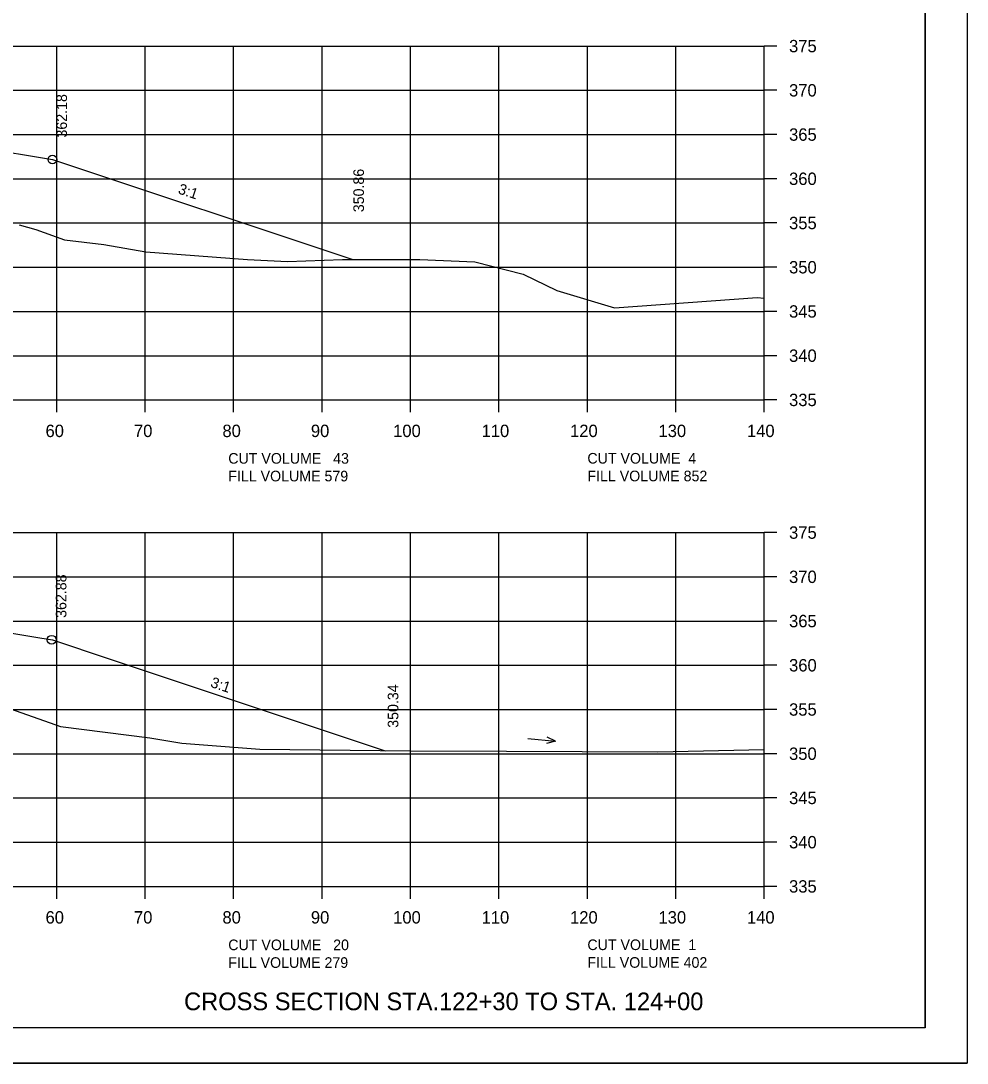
# Model space of a CAD drawing. Extents: x 1374859 to 1376773, y 382242 to 389804.
# Drawn here: x 1376190.5 to 1376297.5, y 384375.1 to 384493 of the extents above; entities that cross this region are included whole.
import ezdxf

# ---------------------------------------------------------------- set-up
doc = ezdxf.new("R2010")
doc.units = 0
for name, color, linetype in [('R_Axis', 7, 'Continuous'), ('R_Axis Annot', 7, 'Continuous'), ('R_Border', 7, 'Continuous'), ('R_Draft', 7, 'Continuous'), ('R_Exist Surface', 7, 'Continuous'), ('R_Fin Surface', 7, 'Continuous'), ('R_Grid', 7, 'Continuous'), ('R_No Plot', 7, 'Continuous'), ('R_Water Annot', 7, 'Continuous'), ('R_Xsect Elev', 7, 'Continuous'), ('R_Xsect Slope', 7, 'Continuous')]:
    doc.layers.add(name, color=color, linetype=linetype)

msp = doc.modelspace()

# ---------------------------------------------------------------- linework, layer by layer
at = {"layer": 'R_Axis'}
for p, q in [((1376274.57, 384450.1), (1376274.57, 384490.1)), ((1376275.97, 384490.1), (1376274.57, 384490.1)), ((1376275.97, 384485.1), (1376274.57, 384485.1)), ((1376275.97, 384480.1), (1376274.57, 384480.1)), ((1376275.97, 384475.1), (1376274.57, 384475.1)), ((1376275.97, 384470.1), (1376274.57, 384470.1)), ((1376275.97, 384465.1), (1376274.57, 384465.1)), ((1376275.97, 384460.1), (1376274.57, 384460.1)), ((1376275.97, 384455.1), (1376274.57, 384455.1)), ((1375994.57, 384450.1), (1376274.57, 384450.1)), ((1376194.57, 384448.7), (1376194.57, 384450.1)), ((1376204.57, 384448.7), (1376204.57, 384450.1)), ((1376214.57, 384448.7), (1376214.57, 384450.1)), ((1376224.57, 384448.7), (1376224.57, 384450.1)), ((1376234.57, 384448.7), (1376234.57, 384450.1)), ((1376244.57, 384448.7), (1376244.57, 384450.1)), ((1376254.57, 384448.7), (1376254.57, 384450.1)), ((1376264.57, 384448.7), (1376264.57, 384450.1)), ((1376274.57, 384448.7), (1376274.57, 384450.1)), ((1376275.97, 384450.1), (1376274.57, 384450.1)), ((1376274.57, 384395.1), (1376274.57, 384435.1)), ((1376275.97, 384435.1), (1376274.57, 384435.1)), ((1376275.97, 384430.1), (1376274.57, 384430.1)), ((1376275.97, 384425.1), (1376274.57, 384425.1)), ((1376275.97, 384420.1), (1376274.57, 384420.1)), ((1376275.97, 384415.1), (1376274.57, 384415.1)), ((1376275.97, 384410.1), (1376274.57, 384410.1)), ((1376275.97, 384405.1), (1376274.57, 384405.1)), ((1376275.97, 384400.1), (1376274.57, 384400.1)), ((1375994.57, 384395.1), (1376274.57, 384395.1)), ((1376194.57, 384393.7), (1376194.57, 384395.1)), ((1376204.57, 384393.7), (1376204.57, 384395.1)), ((1376214.57, 384393.7), (1376214.57, 384395.1)), ((1376224.57, 384393.7), (1376224.57, 384395.1)), ((1376234.57, 384393.7), (1376234.57, 384395.1)), ((1376244.57, 384393.7), (1376244.57, 384395.1)), ((1376254.57, 384393.7), (1376254.57, 384395.1)), ((1376264.57, 384393.7), (1376264.57, 384395.1)), ((1376274.57, 384393.7), (1376274.57, 384395.1)), ((1376275.97, 384395.1), (1376274.57, 384395.1))]:
    msp.add_line(p, q, dxfattribs=at)
at = {"layer": 'R_Border'}
for q in [(1376292.75, 384584.56), (1375976.57, 384379.1)]:
    msp.add_line((1376292.75, 384379.1), q, dxfattribs=at)
at = {"layer": 'R_Exist Surface'}
for points in [[(1376190.33, 384469.88), (1376192.22, 384469.36), (1376195.45, 384468.19), (1376199.89, 384467.66), (1376204.66, 384466.85), (1376216.14, 384465.96), (1376220.67, 384465.74), (1376226.89, 384465.96), (1376235.62, 384465.98), (1376241.83, 384465.72), (1376247.3, 384464.31), (1376251.11, 384462.46), (1376257.64, 384460.52), (1376273.78, 384461.69), (1376274.57, 384461.6)], [(1376189.36, 384415.18), (1376195, 384413.18), (1376205.12, 384411.9), (1376208.73, 384411.28), (1376217.54, 384410.6), (1376234.53, 384410.41), (1376245.43, 384410.37), (1376262.55, 384410.31), (1376274.57, 384410.58)]]:
    msp.add_lwpolyline(points, dxfattribs=at)
at = {"layer": 'R_Fin Surface'}
for points in [[(1376046.15, 384465.48), (1376051.59, 384463.67), (1376075.09, 384471.5), (1376083.13, 384472.85), (1376097.09, 384475.17), (1376105.09, 384475.79), (1376134.59, 384478.06), (1376164.09, 384480.33), (1376172.09, 384480.95), (1376185.9, 384478.64), (1376194.09, 384477.28), (1376228.04, 384465.96)], [(1376064.09, 384413.54), (1376073.29, 384416.61), (1376075.08, 384417.21), (1376081.72, 384418.31), (1376083.13, 384418.55), (1376094.64, 384420.47), (1376097.08, 384420.87), (1376103.69, 384421.38), (1376105.08, 384421.49), (1376110.14, 384421.88), (1376134.58, 384423.76), (1376158.89, 384425.63), (1376164.08, 384426.03), (1376165.47, 384426.14), (1376172.08, 384426.65), (1376183.48, 384424.75), (1376185.9, 384424.35), (1376192.66, 384423.22), (1376194.08, 384422.98), (1376200.51, 384420.84), (1376231.7, 384410.44)]]:
    msp.add_lwpolyline(points, dxfattribs=at)
at = {"layer": 'R_Grid'}
for p, q in [((1375994.57, 384490.1), (1376274.57, 384490.1)), ((1376194.57, 384450.1), (1376194.57, 384490.1)), ((1376204.57, 384450.1), (1376204.57, 384490.1)), ((1376214.57, 384450.1), (1376214.57, 384490.1)), ((1376224.57, 384450.1), (1376224.57, 384490.1)), ((1376234.57, 384450.1), (1376234.57, 384490.1)), ((1376244.57, 384450.1), (1376244.57, 384490.1)), ((1376254.57, 384450.1), (1376254.57, 384490.1)), ((1376264.57, 384450.1), (1376264.57, 384490.1)), ((1376274.57, 384450.1), (1376274.57, 384490.1)), ((1375994.57, 384485.1), (1376274.57, 384485.1)), ((1375994.57, 384480.1), (1376274.57, 384480.1)), ((1375994.57, 384475.1), (1376274.57, 384475.1)), ((1375994.57, 384470.1), (1376274.57, 384470.1)), ((1375994.57, 384465.1), (1376274.57, 384465.1)), ((1375994.57, 384460.1), (1376274.57, 384460.1)), ((1375994.57, 384455.1), (1376274.57, 384455.1)), ((1375994.57, 384450.1), (1376274.57, 384450.1)), ((1375994.57, 384435.1), (1376274.57, 384435.1)), ((1376194.57, 384395.1), (1376194.57, 384435.1)), ((1376204.57, 384395.1), (1376204.57, 384435.1)), ((1376214.57, 384395.1), (1376214.57, 384435.1)), ((1376224.57, 384395.1), (1376224.57, 384435.1)), ((1376234.57, 384395.1), (1376234.57, 384435.1)), ((1376244.57, 384395.1), (1376244.57, 384435.1)), ((1376254.57, 384395.1), (1376254.57, 384435.1)), ((1376264.57, 384395.1), (1376264.57, 384435.1)), ((1376274.57, 384395.1), (1376274.57, 384435.1)), ((1375994.57, 384430.1), (1376274.57, 384430.1)), ((1375994.57, 384425.1), (1376274.57, 384425.1)), ((1375994.57, 384420.1), (1376274.57, 384420.1)), ((1375994.57, 384415.1), (1376274.57, 384415.1)), ((1375994.57, 384410.1), (1376274.57, 384410.1)), ((1375994.57, 384405.1), (1376274.57, 384405.1)), ((1375994.57, 384400.1), (1376274.57, 384400.1)), ((1375994.57, 384395.1), (1376274.57, 384395.1))]:
    msp.add_line(p, q, dxfattribs=at)
at = {"layer": 'R_No Plot'}
msp.add_line((1375964.17, 384375.12), (1376297.5, 384375.12), dxfattribs=at)
for points in [[(1375964.16, 384588.45), (1376297.5, 384588.45), (1376297.5, 384375.12), (1375964.16, 384375.12)], [(1376210.49, 384584.56), (1376210.49, 384574.68), (1376246.22, 384574.68), (1376246.22, 384571.76), (1376269.42, 384571.76), (1376269.42, 384547.43), (1376292.75, 384547.43), (1376292.75, 384379.1), (1375976.57, 384379.1), (1375976.57, 384584.56)]]:
    msp.add_lwpolyline(points, close=True, dxfattribs=at)
for centre in [(1376194.09, 384477.28), (1376194.01, 384422.98)]:
    msp.add_circle(centre, 0.5, dxfattribs=at)
at = {"layer": 'R_Water Annot'}
for p, q in [((1376247.83, 384411.83), (1376250.95, 384411.53)), ((1376250.95, 384411.53), (1376249.96, 384411.27)), ((1376250.95, 384411.53), (1376250.03, 384411.97))]:
    msp.add_line(p, q, dxfattribs=at)

# ---------------------------------------------------------------- texts
at = {"layer": 'R_Axis Annot'}
for s, height, p in [('375', 1.4, (1376277.37, 384489.4)), ('370', 1.4, (1376277.37, 384484.4)), ('365', 1.4, (1376277.37, 384479.4)), ('360', 1.4, (1376277.37, 384474.4)), ('355', 1.4, (1376277.37, 384469.4)), ('350', 1.4, (1376277.37, 384464.4)), ('345', 1.4, (1376277.37, 384459.4)), ('340', 1.4, (1376277.37, 384454.4)), ('335', 1.4, (1376277.37, 384449.4)), ('60', 1.4, (1376193.31, 384445.9)), ('70', 1.4, (1376203.31, 384445.9)), ('80', 1.4, (1376213.31, 384445.9)), ('90', 1.4, (1376223.31, 384445.9)), ('100', 1.4, (1376232.61, 384445.9)), ('110', 1.4, (1376242.61, 384445.9)), ('120', 1.4, (1376252.61, 384445.9)), ('130', 1.4, (1376262.61, 384445.9)), ('140', 1.4, (1376272.61, 384445.9)), ('CUT VOLUME   43', 1.2, (1376213.97, 384442.89)), ('CUT VOLUME  4', 1.2, (1376254.57, 384442.9)), ('FILL VOLUME 579', 1.2, (1376213.97, 384440.89)), ('FILL VOLUME 852', 1.2, (1376254.57, 384440.9)), ('375', 1.4, (1376277.37, 384434.4)), ('370', 1.4, (1376277.37, 384429.4)), ('365', 1.4, (1376277.37, 384424.4)), ('360', 1.4, (1376277.37, 384419.4)), ('355', 1.4, (1376277.37, 384414.4)), ('350', 1.4, (1376277.37, 384409.4)), ('345', 1.4, (1376277.37, 384404.4)), ('340', 1.4, (1376277.37, 384399.4)), ('335', 1.4, (1376277.37, 384394.4)), ('60', 1.4, (1376193.31, 384390.9)), ('70', 1.4, (1376203.31, 384390.9)), ('80', 1.4, (1376213.31, 384390.9)), ('90', 1.4, (1376223.31, 384390.9)), ('100', 1.4, (1376232.61, 384390.9)), ('110', 1.4, (1376242.61, 384390.9)), ('120', 1.4, (1376252.61, 384390.9)), ('130', 1.4, (1376262.61, 384390.9)), ('140', 1.4, (1376272.61, 384390.9)), ('CUT VOLUME   20', 1.2, (1376213.97, 384387.89)), ('CUT VOLUME  1', 1.2, (1376254.57, 384387.9)), ('FILL VOLUME 279', 1.2, (1376213.97, 384385.89)), ('FILL VOLUME 402', 1.2, (1376254.57, 384385.9))]:
    msp.add_text(s, height=height, dxfattribs=at).set_placement(p)
at = {"layer": 'R_Draft'}
msp.add_text('CROSS SECTION STA.122+30 TO STA. 124+00', height=2, dxfattribs=at).set_placement((1376208.97, 384381.1))
at = {"layer": 'R_Xsect Elev'}
for s, p in [('362.18', (1376195.74, 384479.76)), ('350.86', (1376229.31, 384471.32)), ('362.88', (1376195.67, 384425.46)), ('350.34', (1376233.2, 384413.03))]:
    msp.add_text(s, height=1.2, rotation=90, dxfattribs=at).set_placement(p)
at = {"layer": 'R_Xsect Slope'}
for rotation, p in [(341.5651, (1376208.21, 384473.46)), (341.5644, (1376211.88, 384417.67))]:
    msp.add_text('3:1', height=1.2, rotation=rotation, dxfattribs=at).set_placement(p)

doc.saveas('drawing.dxf')
